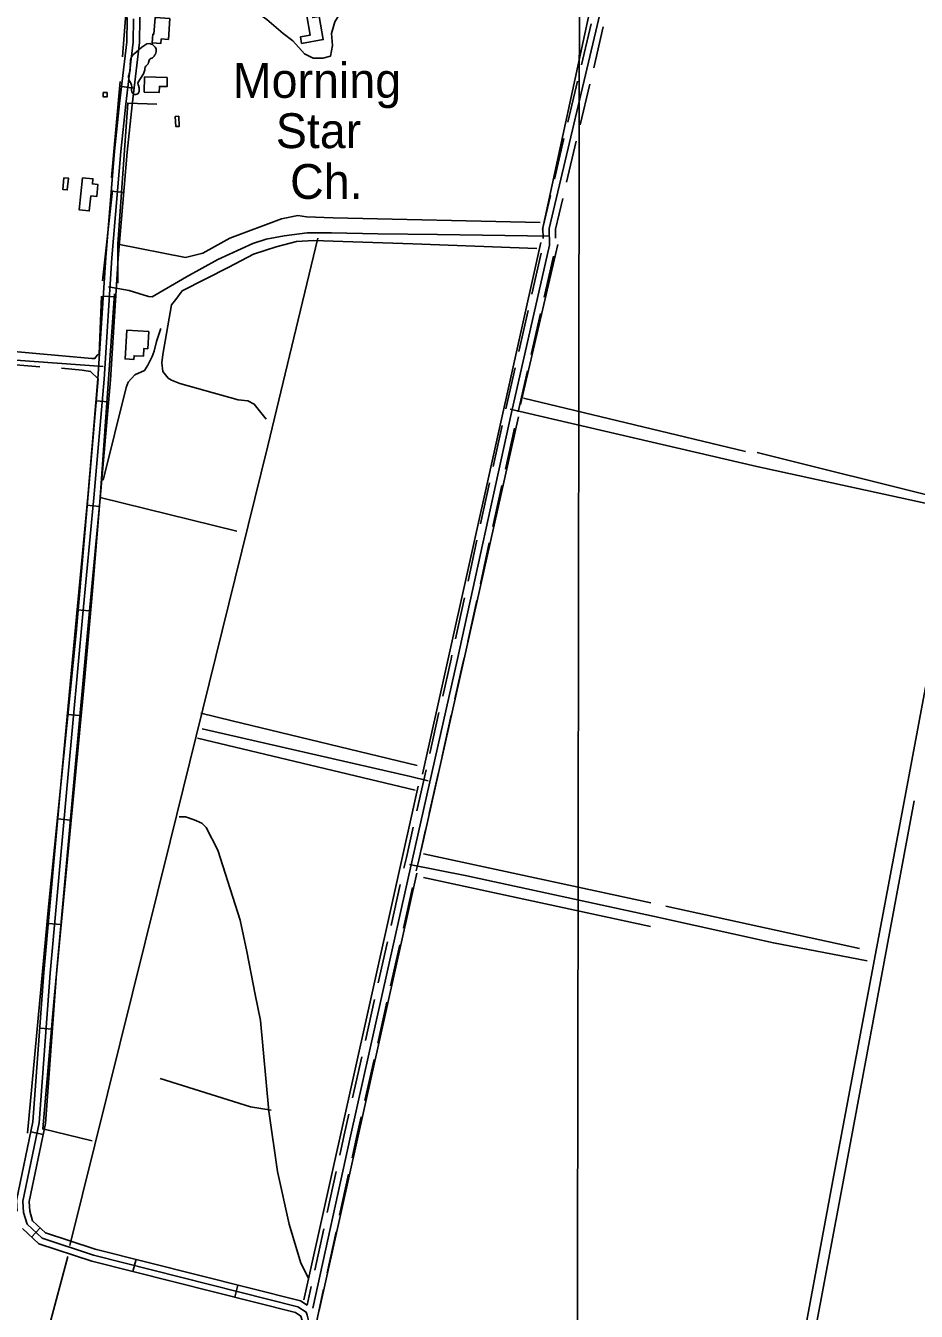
# Model space of a CAD drawing. Extents: x 3219052 to 3256913, y 800770 to 826146.
# Drawn here: x 3227146 to 3229267, y 808063 to 811124 of the extents above; entities that cross this region are included whole.
import ezdxf

# ---------------------------------------------------------------- set-up
doc = ezdxf.new("R2010")
doc.units = 0
for name, color, linetype in [('V-BLDG-OTLN', 7, 'Continuous'), ('V-DTCH-CNTR', 7, 'Continuous'), ('V-GRID-MAJR', 7, 'Continuous'), ('V-ROAD-CNTR', 7, 'Continuous'), ('V-SITE-OTLN-IDEN', 7, 'Continuous'), ('V-SITE-VEGE', 7, 'Continuous'), ('V-TOPO-SHOR', 7, 'Continuous')]:
    doc.layers.add(name, color=color, linetype=linetype)

msp = doc.modelspace()

# ---------------------------------------------------------------- linework, layer by layer
at = {"layer": 'V-BLDG-OTLN'}
for points in [[(3227489, 811141), (3227485.5, 811091.4), (3227468.3, 811092.6), (3227467.6, 811082), (3227446.7, 811083.5), (3227448.1, 811103.8), (3227450.8, 811103.6), (3227453.6, 811143.5)], [(3227844.9, 811146.1), (3227854.5, 811090.8), (3227802.8, 811081.9), (3227800.1, 811097.4), (3227823.2, 811101.4), (3227814.4, 811152.4), (3227827.4, 811154.6), (3227829.3, 811143.4)], [(3227482.8, 811000.7), (3227482.3, 810978.9), (3227464.1, 810979.3), (3227463.7, 810965), (3227427.8, 810965.8), (3227428.7, 811002)], [(3227330, 810964.9), (3227339.5, 810964.7), (3227339.3, 810954.6), (3227329.8, 810954.8)], [(3227501.9, 810908), (3227510.1, 810908.4), (3227511.5, 810884.1), (3227503.3, 810883.6)], [(3227236.5, 810762.1), (3227247.5, 810761), (3227244.7, 810733), (3227233.7, 810734.1)], [(3227280.7, 810762), (3227305.8, 810759.4), (3227304.6, 810747.1), (3227317.8, 810745.7), (3227314.9, 810717.4), (3227300.8, 810718.9), (3227297.1, 810683.1), (3227272.7, 810685.6)], [(3227439, 810395.8), (3227436.3, 810354.9), (3227427.1, 810355.5), (3227425.9, 810336.9), (3227403.6, 810338.3), (3227403, 810329.2), (3227382.4, 810330.5), (3227386.8, 810399.2)]]:
    msp.add_lwpolyline(points, close=True, dxfattribs=at)
at = {"layer": 'V-DTCH-CNTR'}
for points in [[(3227343.2, 810502), (3227392.4, 810493.8), (3227438.3, 810479.4), (3227446.7, 810478.1), (3227528.5, 810525.9), (3227603, 810567.7), (3227686.8, 810605.3), (3227718.4, 810615.6), (3227761.3, 810623.3), (3227816.1, 810631.1), (3227874, 810631), (3227984.2, 810628.8), (3228126.5, 810626.9), (3228394.3, 810622.6)], [(3227330.5, 810312.8), (3227011.7, 810335.3), (3226754.5, 810358.6), (3226576.8, 810387.4)], [(3228299.9, 810210.9), (3228886.9, 810074.4), (3229350.3, 809974)], [(3227566.3, 809449.9), (3228061.9, 809336.7), (3228104, 809326.3)], [(3228059.6, 809126.6), (3228196.7, 809099.4), (3228643.5, 809003.2), (3228926.9, 808939.9), (3229150, 808897.1)]]:
    msp.add_lwpolyline(points, dxfattribs=at)
at = {"layer": 'V-GRID-MAJR'}
msp.add_spline([(3228457.1, 806177.4), (3228466, 812237.7), (3228474.8, 818299.9), (3228483.6, 824362.1), (3228483.6, 824364)], degree=3, dxfattribs=at)
at = {"layer": 'V-ROAD-CNTR'}
for p, q in [((3227374.1, 810979), (3227403.9, 810975.4)), ((3227349.2, 810729.7), (3227379.1, 810727.2)), ((3227330.2, 810480.2), (3227360.1, 810478.2)), ((3227312.9, 810231.1), (3227342.8, 810228.5)), ((3227291.5, 809982.1), (3227321.3, 809979.3)), ((3227267.9, 809733.3), (3227297.7, 809730.4)), ((3227244.7, 809484.3), (3227274.6, 809481.5)), ((3227221.8, 809235.3), (3227251.7, 809232.6)), ((3227199.4, 808986.3), (3227229.3, 808983.6)), ((3227179.2, 808736.9), (3227209.1, 808734.7)), ((3227157.8, 808490), (3227187.2, 808483.9)), ((3227159.4, 808239.8), (3227179.9, 808261.7)), ((3227401, 808157.6), (3227408.4, 808186.7)), ((3227643.4, 808096.4), (3227650.8, 808125.5))]:
    msp.add_line(p, q, dxfattribs=at)
for points in [[(3227829.9, 808070), (3227919, 808479.8), (3228067.1, 809140.4), (3228173.4, 809612.8), (3228302.6, 810203), (3228393.4, 810601.3), (3228392.5, 810641), (3228517.4, 811168.5), (3228525.4, 811238.6)], [(3227125.2, 808301), (3227123.5, 808326.6), (3227162.9, 808514.1), (3227188.8, 808869.3), (3227230.8, 809334.5), (3227267.1, 809724.9), (3227293.3, 810001.1), (3227317.4, 810283.3), (3227336.1, 810572.3), (3227357.2, 810825.6), (3227369.4, 810939.1), (3227386.7, 811085.7), (3227387.5, 811139.6), (3227384.4, 811166.8), (3227386.4, 811205)], [(3227816.2, 808077.4), (3227800.3, 808087.7), (3227311.3, 808211.2), (3227192.4, 808250), (3227162.1, 808278.3), (3227155.3, 808301.2), (3227153.7, 808324.5), (3227192.6, 808509.9), (3227218.7, 808866.9), (3227260.7, 809331.7), (3227296.9, 809722.1), (3227323.2, 809998.4), (3227347.3, 810281.1), (3227366.1, 810570.1), (3227387.1, 810822.8), (3227399.2, 810935.8), (3227416.7, 811083.8), (3227417.5, 811141.1), (3227414.5, 811167.7), (3227416.4, 811203.4)], [(3227469, 806476.2), (3227483.2, 806550.6), (3227684.9, 807445.7), (3227820.4, 808029.8), (3227819.4, 808040.9), (3227815.8, 808053.5), (3227813.5, 808061.2), (3227794.2, 808073.8), (3227307.2, 808196.8), (3227184.6, 808236.8), (3227148.9, 808270.1), (3227140.4, 808298.5), (3227138.6, 808325.5), (3227177.8, 808512), (3227203.8, 808868.1), (3227245.7, 809333.1), (3227282, 809723.5), (3227308.2, 809999.7), (3227332.4, 810282.2), (3227351.1, 810571.2), (3227372.2, 810824.2), (3227384.3, 810937.4), (3227401.7, 811084.8), (3227402.5, 811140.3)], [(3228469.4, 811030.8), (3228492.4, 811128.1)], [(3228498.6, 811023.9), (3228521.6, 811121.2)], [(3228437.1, 810894.6), (3228460.2, 810991.9)], [(3228466.3, 810887.7), (3228489.4, 810985)], [(3228404.9, 810758.3), (3228427.9, 810855.7)], [(3228434.1, 810751.4), (3228457.1, 810848.7)], [(3228378, 810617.7), (3228377.5, 810642.6), (3228395.7, 810719.4)], [(3228408, 810618.4), (3228407.6, 810639.4), (3228424.9, 810712.5)], [(3228351.4, 810484.5), (3228373.6, 810582)], [(3228380.6, 810477.8), (3228402.9, 810575.3)], [(3228320.3, 810348), (3228342.5, 810445.5)], [(3228349.5, 810341.3), (3228371.7, 810438.8)], [(3228289.1, 810211.5), (3228311.4, 810309)], [(3228318.4, 810204.8), (3228340.6, 810302.3)], [(3228259.1, 810074.6), (3228280.5, 810172.3)], [(3228288.4, 810068.2), (3228309.8, 810165.9)], [(3228229.2, 809937.8), (3228250.6, 810035.5)], [(3228258.5, 809931.4), (3228279.9, 810029.1)], [(3228199.3, 809801.1), (3228220.6, 809898.8)], [(3228228.6, 809794.7), (3228250, 809892.3)], [(3228169.3, 809664.3), (3228190.7, 809762)], [(3228198.6, 809657.9), (3228220, 809755.6)], [(3228138.9, 809527.7), (3228158.8, 809616), (3228160.8, 809625.2)], [(3228168.2, 809521.2), (3228188, 809609.5), (3228190.1, 809618.8)], [(3228108.2, 809391.2), (3228130.1, 809488.7)], [(3228137.4, 809384.6), (3228159.4, 809482.1)], [(3228077.4, 809254.6), (3228099.4, 809352.1)], [(3228106.7, 809248), (3228128.7, 809345.5)], [(3228046.7, 809118), (3228052.5, 809143.7), (3228068.7, 809215.5)], [(3228076, 809111.4), (3228081.8, 809137.1), (3228097.9, 809209)], [(3228016.1, 808981.4), (3228038, 809078.9)], [(3228045.4, 808974.8), (3228067.3, 809072.4)], [(3227985.5, 808844.8), (3228007.4, 808942.3)], [(3228014.7, 808838.2), (3228036.6, 808935.8)], [(3227954.8, 808708.1), (3227976.7, 808805.7)], [(3227984.1, 808701.6), (3228006, 808799.2)], [(3227924.2, 808571.5), (3227946.1, 808669.1)], [(3227953.5, 808565), (3227975.4, 808662.6)], [(3227893.9, 808434.8), (3227904.4, 808483), (3227915.5, 808532.5)], [(3227923.2, 808428.4), (3227933.6, 808476.5), (3227944.7, 808525.9)], [(3227864.1, 808298), (3227885.4, 808395.7)], [(3227893.5, 808291.6), (3227914.7, 808389.3)], [(3227454.2, 806479), (3227468.6, 806553.7), (3227670.3, 807449), (3227805.2, 808030.9), (3227804.6, 808038.2), (3227801.4, 808049.3), (3227800.7, 808051.7), (3227788.1, 808059.9), (3227303, 808182.4), (3227176.8, 808223.5), (3227137.9, 808259.9)], [(3227834.4, 808161.2), (3227855.6, 808258.9)], [(3227863.7, 808154.8), (3227885, 808252.5)], [(3227816.2, 808077.4), (3227825.9, 808122.1)], [(3227835.1, 808021.7), (3227855.2, 808115.7)]]:
    msp.add_lwpolyline(points, dxfattribs=at)
at = {"layer": 'V-SITE-VEGE'}
msp.add_lwpolyline([(3227434.1, 811080.8), (3227441, 811081.4), (3227443.1, 811081.2), (3227445.3, 811080.4), (3227447.7, 811079.3), (3227449.3, 811077.8), (3227451.1, 811075.8), (3227453.8, 811073), (3227455.2, 811070.5), (3227456, 811068.2), (3227456, 811062.6), (3227455.7, 811059.7), (3227454.4, 811056.5), (3227453.4, 811054.3), (3227451.6, 811051.6), (3227447.5, 811047.7), (3227442, 811045.2), (3227440.1, 811043.4), (3227438.5, 811036.1), (3227437.5, 811033.4), (3227435.4, 811031.5), (3227432, 811027.6), (3227430.3, 811024.9), (3227429.4, 811022), (3227429.1, 811019.1), (3227428.1, 811013.9), (3227426, 811009.4), (3227424.3, 811006.7), (3227413.8, 810989.6), (3227413, 810987), (3227413.6, 810984.1), (3227414.4, 810981.6), (3227415.9, 810976.3), (3227416.2, 810972.6), (3227416, 810970), (3227415.7, 810967.2), (3227414.4, 810964), (3227412.6, 810962), (3227407.8, 810959.8), (3227404.8, 810960), (3227402.8, 810960.9), (3227400.9, 810962.9), (3227398.4, 810966.9), (3227397.6, 810970.7), (3227397.8, 810973.5), (3227398.4, 810976.5), (3227398.3, 810978.9), (3227397.8, 810982.1), (3227395.9, 810986.9), (3227394.9, 810988.7), (3227393.5, 810990.9), (3227391.9, 810994.3), (3227390.2, 811000.7), (3227390.2, 811003.9), (3227391.1, 811006.6), (3227392.4, 811009.3), (3227394, 811014.9), (3227394.4, 811018.3), (3227394.7, 811023.6), (3227394.9, 811029), (3227394.7, 811031.7), (3227395.2, 811039.9), (3227395.6, 811042.9), (3227396.2, 811046), (3227398.5, 811050.9), (3227401.8, 811055.1), (3227403.6, 811056.8), (3227414.2, 811065.9), (3227416.3, 811068.3), (3227421.9, 811072.6), (3227424.3, 811074.1)], close=True, dxfattribs=at)
at = {"layer": 'V-TOPO-SHOR'}
for p, q in [((3228376.4, 810639), (3228501.5, 811214.8)), ((3227376.2, 811050), (3227384.1, 811152.6)), ((3227370.9, 810990.9), (3227349.9, 810762.6)), ((3227352.4, 810731.8), (3227328.9, 810516.3)), ((3227365, 810603.5), (3227364.8, 810511.1)), ((3228090.6, 809341.8), (3228372.9, 810608)), ((3228324.6, 810222.1), (3228412.9, 810602.8)), ((3228331.6, 810237.1), (3228859.9, 810110.3)), ((3228088, 809161.1), (3228319.4, 810192.3)), ((3228888.2, 810107.6), (3229354.9, 809991.2)), ((3228073.1, 809303.6), (3227555, 809427.9)), ((3227808, 808090), (3228080.8, 809313.3)), ((3228093.3, 809152.2), (3228634.4, 809035.6)), ((3228077.6, 809105.8), (3227844.4, 808064.8)), ((3228093.1, 809095.7), (3228634.3, 808979.1)), ((3228670.4, 809027.8), (3229132, 808926.8))]:
    msp.add_line(p, q, dxfattribs=at)
for points in [[(3227917.9, 811179.7), (3227894.7, 811154.1), (3227881.9, 811133.6), (3227874.1, 811105.4), (3227876.6, 811077.1), (3227871.4, 811051.5), (3227853.5, 811046.4), (3227830.4, 811046.4), (3227809.9, 811056.7), (3227781.7, 811087.6), (3227758.6, 811105.6), (3227720.2, 811139), (3227694.6, 811157.1), (3227674.1, 811164.8), (3227638.2, 811175.1), (3227602.3, 811185.5), (3227566.4, 811185.6), (3227507.3, 811183.1), (3227422.7, 811180.7)], [(3229557.8, 810980.3), (3229372.9, 809998.2), (3229235.5, 809264.3), (3229073.4, 808400), (3228864.7, 807281.5), (3228714.4, 806498.3), (3228652.2, 806177.2)], [(3227458.1, 810936.9), (3227388.8, 810939.6), (3227365, 810603.5), (3227526.6, 810572.4), (3227567.7, 810582.5), (3227631.9, 810618.3), (3227755.2, 810664.3), (3227793.7, 810671.9), (3227814.2, 810669.3), (3227878.3, 810666.6), (3228371, 810655.3)], [(3227250.8, 808219.5), (3227489.5, 809181.5), (3227722.2, 810123.3), (3227841.2, 810617.8)], [(3227718.2, 810187.1), (3227690.1, 810223), (3227674.7, 810230.8), (3227651.6, 810233.4), (3227513.1, 810272.2), (3227492.6, 810279.9), (3227484.9, 810285.1), (3227472.1, 810300.5), (3227469.6, 810321), (3227472.2, 810341.5), (3227493, 810459.5), (3227503.3, 810472.3), (3227518.7, 810492.8), (3227629.2, 810549.1), (3227688.3, 810579.7), (3227742.2, 810597.6), (3227791, 810610.3), (3227832, 810612.8), (3227901.3, 810610.1), (3228068.1, 810604.6), (3228363.2, 810593.7)], [(3226807.7, 810376.3), (3227302.8, 810331.6), (3227310.5, 810331.6), (3227315.7, 810339.3), (3227320.8, 810341.9), (3227326.2, 810480.4)], [(3227648.4, 809920.3), (3227322.7, 810000.6), (3227357.1, 810485.5)], [(3227330.5, 810041.6), (3227384.8, 810262.2), (3227390, 810275), (3227405.4, 810292.9), (3227428.5, 810303.1), (3227436.2, 810316), (3227446.5, 810336.5), (3227451.7, 810349.3), (3227456.9, 810372.4), (3227467.2, 810403.1)], [(3227179.6, 810311.4), (3227025.7, 810324.5), (3226799.9, 810340.4)], [(3227150.1, 808487), (3227200, 809025.7), (3227265.5, 809677.4), (3227318.1, 810282.8), (3227300.2, 810300.8), (3227279.7, 810303.5), (3227230.9, 810308.7)], [(3227322.7, 810000.6), (3227305.1, 809778.3), (3227285.8, 809564.4), (3227212.4, 808799.9), (3227186.1, 808497.2), (3227304.1, 808468.7)], [(3228078.3, 809362.6), (3227637.2, 809468.8), (3227562.8, 809486.9)], [(3228688.7, 806177.1), (3228814.6, 806889.2), (3229092.9, 808371.4), (3229262.3, 809278.3)], [(3227819.2, 808141.7), (3227801.3, 808177.7), (3227773.2, 808270.1), (3227745.3, 808395.9), (3227725, 808539.7), (3227705, 808755.3), (3227692.3, 808816.9), (3227672, 808919.6), (3227656.7, 808994), (3227603.2, 809160.9), (3227575.1, 809214.8), (3227564.8, 809225.1), (3227546.9, 809232.9), (3227526.4, 809240.6), (3227511, 809240.6)], [(3227466, 808617.2), (3227681.4, 808550), (3227730.2, 808542.2)], [(3226751.5, 806179.4), (3226845.5, 806565.7), (3227005.9, 807222.8), (3227202.5, 808029.9), (3227246.2, 808193.2)]]:
    msp.add_lwpolyline(points, dxfattribs=at)

# ---------------------------------------------------------------- texts
at = {"layer": 'V-SITE-OTLN-IDEN'}
for s, p in [('Morning', (3227638.9, 810952.2)), ('Star', (3227741.4, 810832.5)), ('Ch.', (3227775.4, 810711.6))]:
    msp.add_text(s, height=83, dxfattribs=at).set_placement(p)

doc.saveas('drawing.dxf')
